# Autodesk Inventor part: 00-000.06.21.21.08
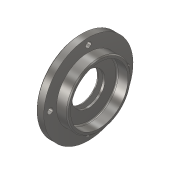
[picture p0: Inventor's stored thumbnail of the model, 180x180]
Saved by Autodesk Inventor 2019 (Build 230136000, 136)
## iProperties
Created: 2019-01
Part Number: 00-000.06.21.21.08
Material: Steel, Mild
Document SubType Name: Modeling
Designer: m.vorobev
Density: 7.85 g/cm^3
Appearance: Semi-Polished
Author: m.vorobev
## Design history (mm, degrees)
derived "00-000.06.21.21.08,09.ipt"
feature "Solid1::00-000.06.21.21.08,09.ipt"
tag "TaggingFeature1"
body "Solid1"
other parameters: "d3" = 52, "d4" = 5, "d5" = 14 deg, "d6" = 69, "d7" = 3.5, "d8" = 12, "B" = 29, "d11" = 2, "d12" = 1.5, "d16" = 9, "d21" = 24, "d22" = 118 deg, "d24" = 360 deg
